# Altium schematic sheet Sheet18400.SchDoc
size A0
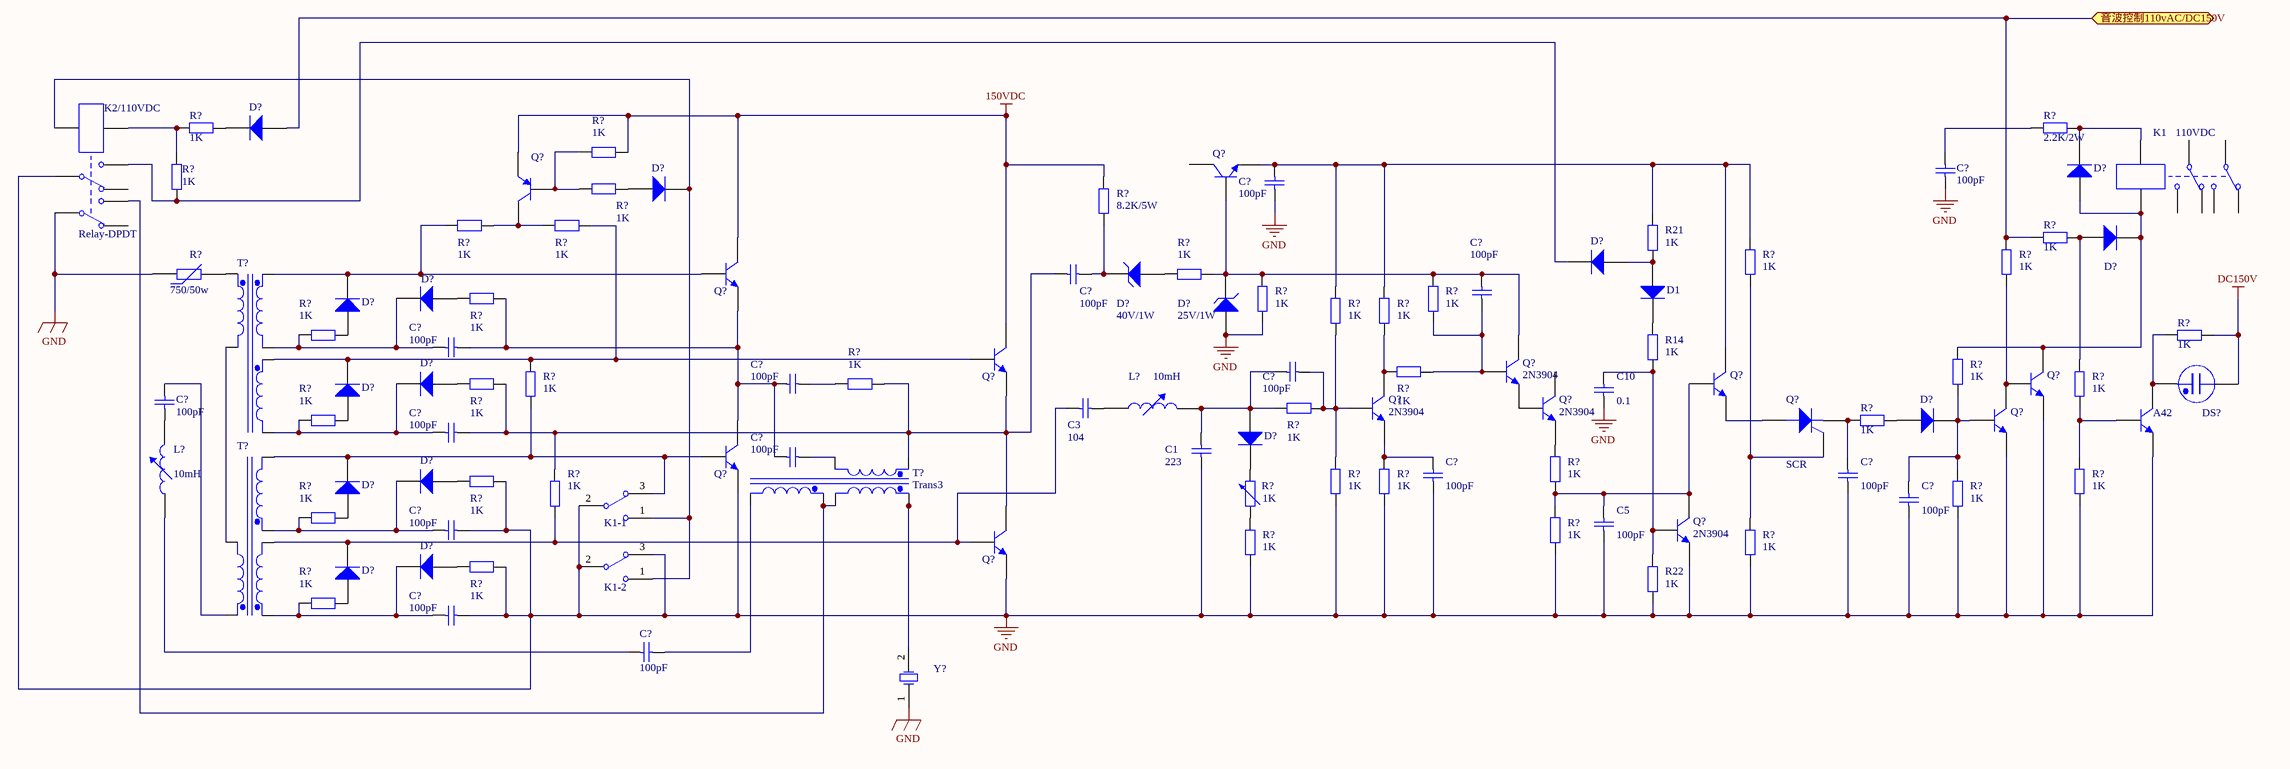
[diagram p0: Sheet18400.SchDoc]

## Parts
(Parts that share a designator on the sheet are numbered #1, #2 ... from top to bottom, then left to right.)
A42  2N3904  [TO-92A]  (value not drawn)
C1  value 223  [C1206]  (hidden comment: Cap Semi)
C3  value 104  [C1206]  (hidden comment: Cap Semi)
C5  value 100pF  [C1206]  (hidden comment: Cap Semi)
C10  value 0.1  [C1206]  (hidden comment: Cap Semi)
C?#1  value 100pF  [C1206]  (hidden comment: Cap Semi)
C?#2  value 100pF  [C1206]  (hidden comment: Cap Semi)
C?#3  value 100pF  [C1206]  (hidden comment: Cap Semi)
C?#4  value 100pF  [C1206]  (hidden comment: Cap Semi)
C?#5  value 100pF  [C1206]  (hidden comment: Cap Semi)
C?#6  value 100pF  [C1206]  (hidden comment: Cap Semi)
C?#7  value 100pF  [C1206]  (hidden comment: Cap Semi)
C?#8  value 100pF  [C1206]  (hidden comment: Cap Semi)
C?#9  value 100pF  [C1206]  (hidden comment: Cap Semi)
C?#10  value 100pF  [C1206]  (hidden comment: Cap Semi)
C?#11  value 100pF  [C1206]  (hidden comment: Cap Semi)
C?#12  value 100pF  [C1206]  (hidden comment: Cap Semi)
C?#13  value 100pF  [C1206]  (hidden comment: Cap Semi)
C?#14  value 100pF  [C1206]  (hidden comment: Cap Semi)
C?#15  value 100pF  [C1206]  (hidden comment: Cap Semi)
C?#16  value 100pF  [C1206]  (hidden comment: Cap Semi)
D1  Diode 1N4007  [DO-41]  (value not drawn)
D?#1  Diode 1N4007  [DO-41]  (value not drawn)
D?#2  Diode 1N4007  [DO-41]  (value not drawn)
D?#3  Diode 1N4007  [DO-41]  (value not drawn)
D?#4  Diode 1N4007  [DO-41]  (value not drawn)
D?#5  Diode 1N4007  [DO-41]  (value not drawn)
D?#6  40V/1W  [DIODE-0.7]
D?#7  Diode 1N4007  [DO-41]  (value not drawn)
D?#8  Diode 1N4007  [DO-41]  (value not drawn)
D?#9  25V/1W  [DIODE-0.7]
D?#10  Diode 1N4007  [DO-41]  (value not drawn)
D?#11  Diode 1N4007  [DO-41]  (value not drawn)
D?#12  Diode 1N4007  [DO-41]  (value not drawn)
D?#13  Diode 1N4007  [DO-41]  (value not drawn)
D?#14  Diode 1N4007  [DO-41]  (value not drawn)
D?#15  Diode 1N4007  [DO-41]  (value not drawn)
D?#16  Diode 1N4007  [DO-41]  (value not drawn)
D?#17  Diode 1N4007  [DO-41]  (value not drawn)
DS?  Neon  [PIN2]  (value not drawn)
K1_110VDC  Relay-DPDT  [DIP-P8]  (value not drawn)
K2/110VDC  Relay-DPDT  [DIP-P8]
L?#1  value 10mH  [AXIAL-0.8]  (hidden comment: Inductor Adj)
L?#2  value 10mH  [AXIAL-0.8]  (hidden comment: Inductor Adj)
Q?#1  2N3906  [TO-92A]  (value not drawn)
Q?#2  2N3904  [TO-92A]  (value not drawn)
Q?#3  2N3904  [TO-92A]  (value not drawn)
Q?#4  2N3904  [TO-92A]  (value not drawn)
Q?#5  2N3904  [TO-92A]
Q?#6  2N3904  [TO-92A]  (value not drawn)
Q?#7  2N3904  [TO-92A]  (value not drawn)
Q?#8  2N3904  [TO-92A]
Q?#9  2N3904  [TO-92A]
Q?#10  SCR  [TO-220-AB]
Q?#11  2N3904  [TO-92A]  (value not drawn)
Q?#12  2N3904  [TO-92A]  (value not drawn)
Q?#13  2N3904  [TO-92A]
Q?#14  2N3904  [TO-92A]  (value not drawn)
R14  value 1K  [AXIAL-0.4]  (hidden comment: Res2)
R21  value 1K  [AXIAL-0.4]  (hidden comment: Res2)
R22  value 1K  [AXIAL-0.4]  (hidden comment: Res2)
R?#1  value 2.2K/2W  [AXIAL-0.4]  (hidden comment: Res2)
R?#2  value 1K  [AXIAL-0.4]  (hidden comment: Res2)
R?#3  value 1K  [AXIAL-0.4]  (hidden comment: Res2)
R?#4  value 1K  [AXIAL-0.4]  (hidden comment: Res2)
R?#5  value 1K  [AXIAL-0.4]  (hidden comment: Res2)
R?#6  value 1K  [AXIAL-0.4]  (hidden comment: Res2)
R?#7  value 1K  [AXIAL-0.4]  (hidden comment: Res2)
R?#8  value 8.2K/5W  [AXIAL-0.4]  (hidden comment: Res2)
R?#9  value 1K  [AXIAL-0.4]  (hidden comment: Res2)
R?#10  value 1K  [AXIAL-0.4]  (hidden comment: Res2)
R?#11  value 1K  [AXIAL-0.4]  (hidden comment: Res2)
R?#12  750/50w  [6-0805]
R?#13  value 1K  [AXIAL-0.4]  (hidden comment: Res2)
R?#14  value 1K  [AXIAL-0.4]  (hidden comment: Res2)
R?#15  value 1K  [AXIAL-0.4]  (hidden comment: Res2)
R?#16  value 1K  [AXIAL-0.4]  (hidden comment: Res2)
R?#17  value 1K  [AXIAL-0.4]  (hidden comment: Res2)
R?#18  value 1K  [AXIAL-0.4]  (hidden comment: Res2)
R?#19  value 1K  [AXIAL-0.4]  (hidden comment: Res2)
R?#20  value 1K  [AXIAL-0.4]  (hidden comment: Res2)
R?#21  value 1K  [AXIAL-0.4]  (hidden comment: Res2)
R?#22  value 1K  [AXIAL-0.4]  (hidden comment: Res2)
R?#23  value 1K  [AXIAL-0.4]  (hidden comment: Res2)
R?#24  value 1K  [AXIAL-0.4]  (hidden comment: Res2)
R?#25  value 1K  [AXIAL-0.4]  (hidden comment: Res2)
R?#26  value 1K  [AXIAL-0.4]  (hidden comment: Res2)
R?#27  value 1K  [AXIAL-0.4]  (hidden comment: Res2)
R?#28  value 1K  [AXIAL-0.4]  (hidden comment: Res2)
R?#29  value 1K  [AXIAL-0.4]  (hidden comment: Res2)
R?#30  value 1K  [AXIAL-0.4]  (hidden comment: Res2)
R?#31  value 1K  [AXIAL-0.4]  (hidden comment: Res2)
R?#32  value 1K  [AXIAL-0.4]  (hidden comment: Res2)
R?#33  value 1K  [AXIAL-0.4]  (hidden comment: Res2)
R?#34  value 1K  [AXIAL-0.4]  (hidden comment: Res2)
R?#35  value 1K  [AXIAL-0.4]  (hidden comment: Res2)
R?#36  value 1K  [AXIAL-0.4]  (hidden comment: Res2)
R?#37  value 1K  [AXIAL-0.4]  (hidden comment: Res2)
R?#38  value 1K  [AXIAL-0.6]  (hidden comment: Res Adj2)
R?#39  value 1K  [AXIAL-0.4]  (hidden comment: Res2)
R?#40  value 1K  [AXIAL-0.4]  (hidden comment: Res2)
R?#41  value 1K  [AXIAL-0.4]  (hidden comment: Res2)
R?#42  value 1K  [AXIAL-0.4]  (hidden comment: Res2)
R?#43  value 1K  [AXIAL-0.4]  (hidden comment: Res2)
S?#1  K1-1  [TL36WW15050]
S?#2  K1-2  [TL36WW15050]
T?#1  Trans3 Ideal  [TRF_6]  (value not drawn)
T?#2  Trans3  [TRF_6]
T?#3  Trans3 Ideal  [TRF_6]  (value not drawn)
Y?  XTAL  [R38]  (value not drawn)

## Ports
音波控制110vAC/DC150V

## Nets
150VDC: Q?#1.1(E) Q?#3.3(C) Q?#4.3(C) R?#3.2 R?#8.2
DC150V: DS?.2 R?#20.2
GND: A42.1(E) C1.1 C5.1 C10.1 C?#1.2 C?#2.1 C?#11.1 C?#12.1 C?#13.1 C?#14.2 C?#15.2 D?#9.1(A) K2/110VDC.1 K2/110VDC.4 Q?#7.1(E) Q?#11.1(E) Q?#12.1(E) Q?#13.1(E) Q?#14.1(E) R22.2 R?#12.1 R?#15.2 R?#31.2 R?#32.2 R?#33.2 R?#34.2 R?#35.2 R?#39.2 R?#40.2 R?#41.2 R?#42.1 S?#1.2 S?#2.2 S?#2.3 Y?.1(OSC1)
音波控制110vAC/DC150V: D?#1.1(A) R?#9.1 R?#11.1 ; port 音波控制110vAC/DC150V
NetA42_2: A42.2(B) R?#24.2 R?#34.1
NetA42_3: A42.3(C) DS?.1 R?#20.1
NetC1_2: C1.2 C?#6.1 D?#13.1(A) L?#1.2 R?#29.2
NetC3_1: C3.1 D?#16.2(K) Q?#14.2(B) R?#37.1 T?#3.4(Sec1-)
NetC3_2: C3.2 L?#1.1
NetC5_2: C5.2 Q?#6.2(B) Q?#13.3(C) R?#30.2 R?#39.1
NetC10_2: C10.2 Q?#13.2(B) R14.2 R22.1
NetC?#1_1: C?#1.1 R?#1.1
NetC?#2_2: C?#2.2 Q?#2.1(E) Q?#6.3(C) R21.1 R?#10.1 R?#17.1 R?#18.1
NetC?#3_1: C?#3.1 C?#9.2 Q?#4.1(E) Q?#14.3(C) R?#22.2 R?#23.2 R?#37.2 T?#2.1(Pri+)
NetC?#3_2: C?#3.2 D?#6.2(K) R?#8.1
NetC?#4_1: C?#4.1 Q?#5.2(B) R?#16.2 R?#25.1
NetC?#4_2: C?#4.2 D?#9.2(K) Q?#2.2(B) Q?#5.3(C) R?#14.1 R?#15.1 R?#16.1
NetC?#5_1: C?#5.1 D?#8.2(K) R?#19.1 T?#1.4(Sec1-)
NetC?#5_2: C?#5.2 C?#7.1 C?#10.1 Q?#3.1(E) Q?#12.3(C) R?#13.2
NetC?#6_2: C?#6.2 Q?#8.2(B) R?#17.2 R?#29.1 R?#32.1
NetC?#7_2: C?#7.2 R?#23.1
NetC?#8_1: C?#8.1 L?#2.2
NetC?#8_2: C?#8.2 T?#3.1(Pri+)
NetC?#9_1: C?#9.1 D?#11.2(K) R?#27.1 T?#1.6(Sec2-)
NetC?#10_2: C?#10.2 T?#2.2(Pri-)
NetC?#11_2: C?#11.2 Q?#8.1(E) R?#33.1
NetC?#12_2: C?#12.2 Q?#10.3(K) R?#28.1
NetC?#13_2: C?#13.2 D?#12.2(K) Q?#11.2(B) R?#21.2 R?#35.1
NetC?#14_1: C?#14.1 D?#15.2(K) R?#36.1 T?#3.5(Sec2+)
NetC?#15_1: C?#15.1 D?#17.2(K) R?#43.1 T?#3.3(Sec1+)
NetC?#16_1: C?#16.1 T?#2.6(Sec2-)
NetC?#16_2: C?#16.2 L?#2.1
NetD1_1: D1.1(A) D?#5.1(A) R21.2
NetD1_2: D1.2(K) R14.1
NetD?#1_2: D?#1.2(K) R?#2.1
NetD?#2_1: D?#2.1(A) R?#5.2
NetD?#2_2: D?#2.2(K) K2/110VDC.7 S?#1.1 S?#2.1
NetD?#3_1: D?#3.1(A) D?#4.2(K) K1_110VDC.8 Q?#7.3(C) R?#21.1
NetD?#3_2: D?#3.2(K) K1_110VDC.7 R?#1.2
NetD?#4_1: D?#4.1(A) R?#9.2 R?#24.1
NetD?#5_2: D?#5.2(K) K2/110VDC.6 R?#4.2
NetD?#6_1: D?#6.1(A) R?#14.2
NetD?#7_1: D?#7.1(A) R?#19.2
NetD?#7_2: D?#7.2(K) Q?#3.2(B) R?#6.1 T?#1.3(Sec1+)
NetD?#8_1: D?#8.1(A) R?#13.1
NetD?#10_1: D?#10.1(A) R?#27.2
NetD?#10_2: D?#10.2(K) Q?#4.2(B) R?#7.2 R?#26.2 T?#1.5(Sec2+)
NetD?#11_1: D?#11.1(A) R?#22.1
NetD?#12_1: D?#12.1(A) R?#28.2
NetD?#13_2: D?#13.2(K) R?#38.2
NetD?#14_1: D?#14.1(A) R?#36.2
NetD?#14_2: D?#14.2(K) Q?#12.2(B) R?#26.1 S?#1.3 T?#3.6(Sec2-)
NetD?#15_1: D?#15.1(A) R?#31.1
NetD?#16_1: D?#16.1(A) R?#43.2
NetD?#17_1: D?#17.1(A) R?#41.1
NetK2/110VDC_3: K2/110VDC.3 T?#2.4(Sec1-) T?#2.5(Sec2+)
NetK2/110VDC_8: K2/110VDC.8 R?#2.2 R?#4.1
NetQ?#1_2: Q?#1.2(B) R?#3.1 R?#5.1
NetQ?#1_3: Q?#1.3(C) R?#6.2 R?#7.1
NetQ?#5_1: Q?#5.1(E) Q?#9.2(B)
NetQ?#6_1: Q?#6.1(E) Q?#10.1(A)
NetQ?#7_2: Q?#7.2(B) Q?#11.3(C) R?#11.2
NetQ?#8_3: Q?#8.3(C) R?#18.2 R?#25.2
NetQ?#9_1: Q?#9.1(E) R?#30.1
NetQ?#10_2: Q?#10.2(G) R?#10.2 R?#40.1
NetR?#12_2: R?#12.2 T?#1.1(Pri+)
NetR?#38_1: R?#38.1 R?#42.2
NetT?#1_2: T?#1.2(Pri-) T?#3.2(Pri-)
NetT?#2_3: T?#2.3(Sec1+) Y?.2(OSC2)

Not connected (* = marked no-connect by the designer): K1_110VDC 1 2 3 4 5 6; K2/110VDC 2 5; Q?#2 3(C); Q?#9 3(C)

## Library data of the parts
A42 Q?#2-Q?#9 Q?#11-Q?#14 = 2N3904: NPN General Purpose Amplifier
C1 C3 C5 C10 C?#1-C?#16 = Cap Semi: Capacitor (Semiconductor SIM Model)
D1 D?#1-D?#5 D?#7 D?#8 D?#10-D?#17 = Diode 1N4007: 1 Amp General Purpose Rectifier
D?#6 D?#9 = D Zener: Zener Diode
DS? = Neon: Neon Bulb
K1_110VDC K2/110VDC = Relay-DPDT: Dual-Pole Dual-Throw Relay
L?#1 L?#2 = Inductor Adj: Adjustable Inductor; Set Position: 0.5
Q?#1 = 2N3906: PNP General Purpose Amplifier
Q?#10 = SCR: Silicon Controlled Rectifier
R14 R21 R22 R?#1-R?#11 R?#13-R?#37 R?#39-R?#43 = Res2: Resistor
R?#12 = Res Varistor: Varistor (Voltage-Sensitive Resistor)
R?#38 = Res Adj2: Variable Resistor; Set Position: 0.5
S?#1 S?#2 = SW-SPDT: SPDT Subminiature Toggle Switch, Right Angle Mounting, Vertical Actuation
T?#1 T?#3 = Trans3 Ideal: Three-winding Transformer (Ideal)
T?#2 = Trans3: Three-winding Transformer (Non-Ideal); Sim Note: Enter the turns ratios, Core loss resistance, Magnetising Reactance, Leakage Reactances and Resistances referred to the primary side into the parameter fields.
Y? = XTAL: Crystal Oscillator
